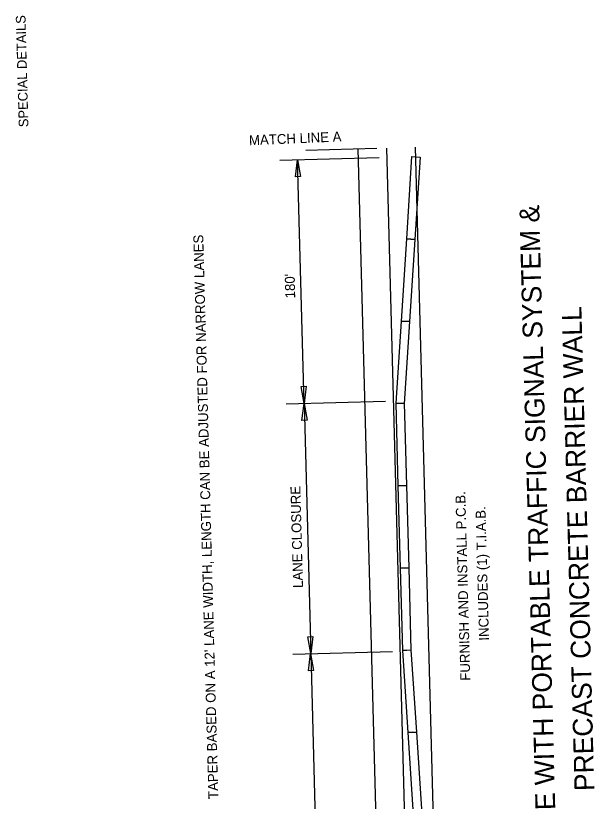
# Model space of a CAD drawing. Extents: x 1929624 to 1935547, y 596315 to 605721.
# Drawn here: x 1930711.6 to 1931062.8, y 597266 to 597742.7 of the extents above; entities that cross this region are included whole.
import ezdxf

# ---------------------------------------------------------------- set-up
doc = ezdxf.new("R2010")
doc.units = 0
for name, color, linetype in [('Default', 7, 'Continuous'), ('R_Border', 7, 'Continuous'), ('R_No Plot', 7, 'Continuous'), ('T_Vehicle Path Rt', 7, 'Continuous')]:
    doc.layers.add(name, color=color, linetype=linetype)

msp = doc.modelspace()

# ---------------------------------------------------------------- linework, layer by layer
at = {"layer": 'Default'}
for p, q in [((1930887.73, 597661.11), (1930930.77, 597662.27)), ((1930937.4, 596998.85), (1930919.6, 597661.97)), ((1930954.78, 596999.31), (1930936.98, 597662.44)), ((1930972.16, 596999.78), (1930954.36, 597662.9)), ((1930871.91, 597655.05), (1930932.24, 597656.67)), ((1930881.42, 597645), (1930882.69, 597655.34)), ((1930886.66, 597507.5), (1930882.69, 597655.34)), ((1930882.69, 597655.34), (1930884.51, 597645.08)), ((1930884.51, 597645.08), (1930881.42, 597645)), ((1930884.84, 597517.76), (1930887.93, 597517.84)), ((1930886.66, 597507.5), (1930884.84, 597517.76)), ((1930887.93, 597517.84), (1930886.66, 597507.5)), ((1930875.88, 597507.21), (1930936.2, 597508.83)), ((1930885.39, 597497.16), (1930886.66, 597507.5)), ((1930886.66, 597507.5), (1930888.48, 597497.24)), ((1930886.79, 597507.51), (1930890.74, 597355.62)), ((1930888.48, 597497.24), (1930885.39, 597497.16)), ((1930888.91, 597365.88), (1930892.01, 597365.96)), ((1930892.01, 597365.96), (1930890.74, 597355.62)), ((1930890.74, 597355.62), (1930888.91, 597365.88)), ((1930879.95, 597355.33), (1930940.28, 597356.95)), ((1930889.33, 597345.27), (1930890.6, 597355.62)), ((1930890.6, 597355.62), (1930892.43, 597345.36)), ((1930890.74, 597355.62), (1930897.44, 597105.99)), ((1930892.43, 597345.36), (1930889.33, 597345.27))]:
    msp.add_line(p, q, dxfattribs=at)
at = {"layer": 'T_Vehicle Path Rt'}
for points in [[(1930948.96, 597607.31), (1930952.18, 597657.21), (1930957.17, 597656.88), (1930953.95, 597606.99)], [(1930945.73, 597557.42), (1930948.96, 597607.31), (1930953.95, 597606.99), (1930950.72, 597557.09)], [(1930942.51, 597507.52), (1930945.73, 597557.42), (1930950.72, 597557.09), (1930947.5, 597507.2)], [(1930943.85, 597457.54), (1930942.51, 597507.52), (1930947.51, 597507.65), (1930948.85, 597457.67)], [(1930945.19, 597407.56), (1930943.85, 597457.54), (1930948.85, 597457.67), (1930950.19, 597407.69)], [(1930946.53, 597357.57), (1930945.19, 597407.56), (1930950.19, 597407.69), (1930951.53, 597357.71)], [(1930949.85, 597307.68), (1930946.53, 597357.57), (1930951.52, 597357.91), (1930954.84, 597308.02)], [(1930953.16, 597257.79), (1930949.85, 597307.68), (1930954.84, 597308.02), (1930958.15, 597258.13)]]:
    msp.add_lwpolyline(points, close=True, dxfattribs=at)

# ---------------------------------------------------------------- texts
at = {"layer": 'Default'}
for s, height, rotation, p in [('MATCH LINE A', 6, 2.3436, (1930853.35, 597664.12)), ('LANE CLOSURE WITH PORTABLE TRAFFIC SIGNAL SYSTEM &', 12, 91.5377, (1931042.21, 597147.6)), ("180'", 6, 91.5377, (1930881.33, 597571.29)), ('PRECAST CONCRETE BARRIER WALL', 12, 91.5377, (1931062.87, 597272.4)), ('LANE CLOSURE', 6, 91.5377, (1930886.05, 597395.52)), ('FURNISH AND INSTALL P.C.B. ', 6, 91.5377, (1930987.58, 597339.26)), ('INCLUDES (1) T.I.A.B.', 6, 91.5377, (1930998.93, 597363.57))]:
    msp.add_text(s, height=height, rotation=rotation, dxfattribs=at).set_placement(p)
at = {"layer": 'R_Border'}
msp.add_text('SPECIAL DETAILS', height=5.862, rotation=91.5377, dxfattribs=at).set_placement((1930719.38, 597675.16))
at = {"layer": 'R_No Plot'}
msp.add_text("TAPER BASED ON A 12' LANE WIDTH, LENGTH CAN BE ADJUSTED FOR NARROW LANES", height=6, rotation=91.5377, dxfattribs=at).set_placement((1930834.65, 597267.46))

doc.saveas('drawing.dxf')
